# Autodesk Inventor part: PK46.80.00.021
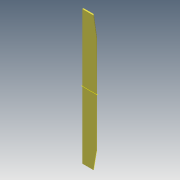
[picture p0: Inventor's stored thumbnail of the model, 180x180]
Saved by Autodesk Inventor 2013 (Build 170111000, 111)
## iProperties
Shininess: 64.0
Length Units: 11269
Angle Units: 11279
Time Units: 11290
Mass Units: 11283
Length Display Precision: 3
Angle Display Precision: 2
Compacted: True
Part Number: PK46.80.00.021
Document SubType Name: Modeling
Created: 2004-12
Designer: Salex
Manufacturer: Standard
Standards Organization: Custom
Material: Steel, Mild
Density: 7.86 g/cm^3
Mass: 136972 g
Surface Area: 15548.2 cm^2
Volume: 17426.4 cm^3
Density: 0.0
Volumn: 0.0
Area: 0.0
PropertySet Name: Model Information
Control State: 0
Master: False
Checked Out: False
Checked Out Date: 2008-10-15
Last Check In Date: 2008-10-15
Author: Salex
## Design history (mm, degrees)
sketch "Sketch1"
  geometry: L1 (280, 0)-(280, 10); L2 (280, 10)-(250, 25); L3 (0, 0)-(0, 25); L4 (0, 0)-(280, 0); L5 (0, 25)-(250, 25)
  constraints: 10 end point, 1 horizontal, 1 parallel, 1 perpendicular, 1 other
  dimensions: "d0" = 280 distance between parallel lines of L3 L1; "d2" = 10 distance of L1.start L1.end; "d16" = 30 distance from line of L2.end L1; "d17" = 25 distance of L3.start L3.end
extrude "Extrusion1" new body sketch "Sketch1" stored distance "d5" = 2650; taper "d6" = 0 deg
chamfer "Chamfer3" distance "d18" = 350; stored, may be unused: second distance "d19" = 60, angle "d26" = 45 deg
chamfer "Chamfer4" distance "d20" = 350; stored, may be unused: second distance "d21" = 60, angle "d27" = 45 deg
chamfer "Chamfer5" distance "d22" = 30; stored, may be unused: second distance "d23" = 15, angle "d28" = 45 deg
chamfer "Chamfer6" distance "d24" = 30; stored, may be unused: second distance "d25" = 15, angle "d29" = 45 deg
workplane "Work Plane1"
body "Solid1"
